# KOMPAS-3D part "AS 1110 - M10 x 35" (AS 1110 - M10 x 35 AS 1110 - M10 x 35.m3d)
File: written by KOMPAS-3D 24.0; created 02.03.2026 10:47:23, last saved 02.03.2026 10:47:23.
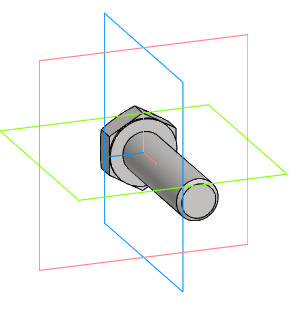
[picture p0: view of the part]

Document properties: Автор: R2D2; Полное имя файла: E:\Работа\Зайцев\GVWR3131M-2W-F-S Задвижка клиновая с выдвижным штоком DN.ru Ду50-200 Ру63\DN200\исходные материалы\AS 1110 - M10 x 35 AS 1110 - M10 x 35.m3d

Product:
- Body: Solid1  | qty 1
- Part/product: AS 1110 - M10 x 35
    Комментарий: Болты и винты   шестигранные точные   метрические ISO
    additional columns: Сталь, мягкая

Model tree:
1. Solid1  (labels: Solid1)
